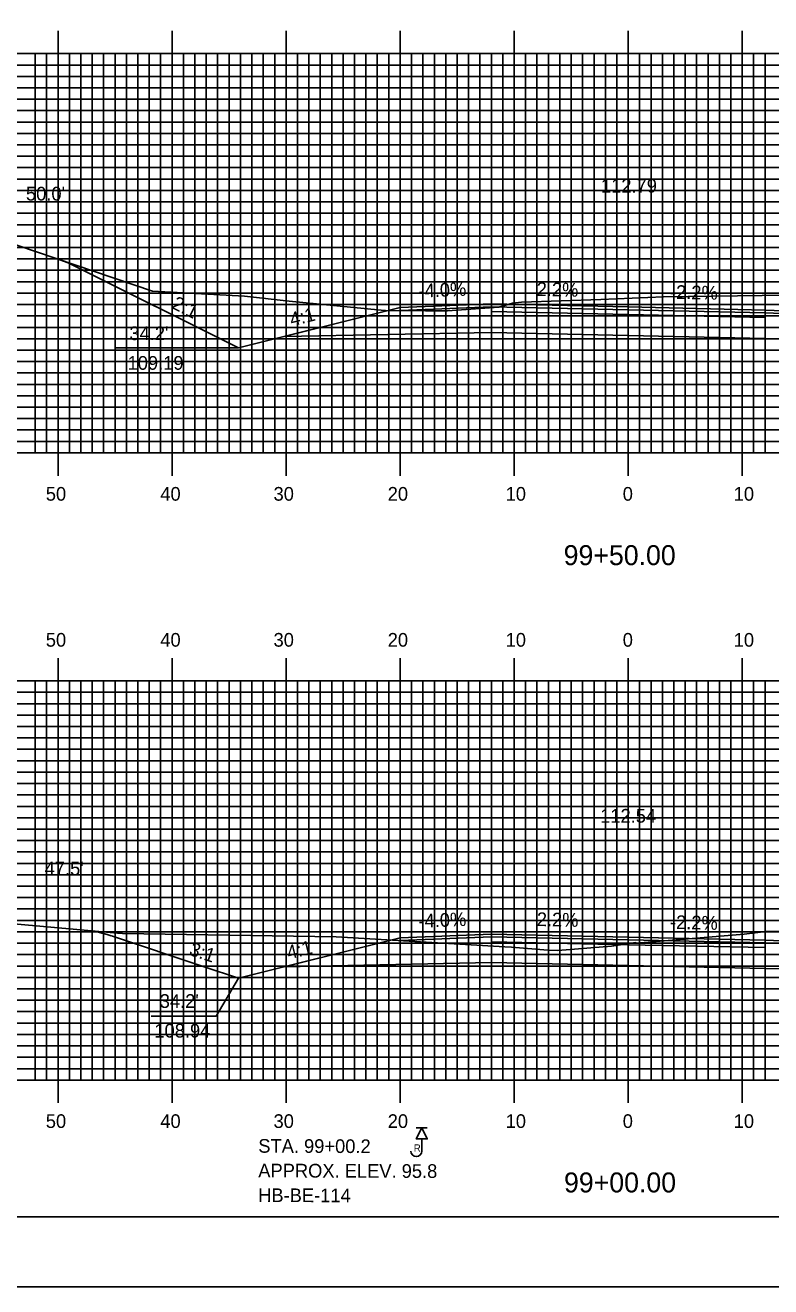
# Model space of a CAD drawing. Extents: x 1766513 to 1766856, y 442591 to 442811.
# Drawn here: x 1766626 to 1766691.4, y 442590.5 to 442701.2 of the extents above; entities that cross this region are included whole.
import ezdxf

# ---------------------------------------------------------------- set-up
doc = ezdxf.new("R2010")
doc.units = 0
for name, color, linetype in [('ANNOTATION', 7, 'Continuous'), ('BORDER', 7, 'Continuous'), ('BORING - REFUSAL', 7, 'Continuous'), ('D_Roadway_Centerline', 7, 'Continuous'), ('D_Roadway_Centerline_Text', 7, 'Continuous'), ('D_Roadway_Edge_Shoulder', 7, 'Continuous'), ('D_Roadway_Edge_TW', 7, 'Continuous'), ('D_Roadway_Pavement', 7, 'Continuous'), ('D_Roadway_SlopeLines', 7, 'Continuous'), ('D_Roadway_SubGrade', 7, 'Continuous'), ('D_Text_Standard', 7, 'Continuous'), ('H_V ANNOTATION', 7, 'Continuous'), ('MAJOR', 7, 'Continuous'), ('MINOR', 7, 'Continuous'), ('PDRAIN', 7, 'Continuous'), ('PLOT BOUNDARY', 7, 'Continuous'), ('S_Roadway_Centerline', 7, 'Continuous')]:
    doc.layers.add(name, color=color, linetype=linetype)

msp = doc.modelspace()

# ---------------------------------------------------------------- linework, layer by layer
at = {"layer": 'ANNOTATION'}
msp.add_lwpolyline([(1766637.09, 442614.28), (1766642.78, 442614.28), (1766644.74, 442617.61)], dxfattribs=at)
msp.add_arc((1766625.79, 442671.15), 10, 63.4315, 71.3181, dxfattribs=at)
at = {"layer": 'BORDER'}
msp.add_lwpolyline([(1766529.31, 442596.67), (1766849.31, 442596.67), (1766849.31, 442806.67), (1766529.31, 442806.67)], close=True, dxfattribs=at)
at = {"layer": 'BORING - REFUSAL'}
for p, q in [((1766661.29, 442604.47), (1766660.33, 442604.47)), ((1766660.81, 442603.51), (1766660.81, 442602.45))]:
    msp.add_line(p, q, dxfattribs=at)
msp.add_lwpolyline([(1766660.81, 442604.47), (1766661.29, 442603.51), (1766660.33, 442603.51)], close=True, dxfattribs=at)
msp.add_arc((1766660.33, 442602.45), 0.485, 180, 0, dxfattribs=at)
at = {"layer": 'D_Roadway_Centerline'}
for p, q in [((1766641.74, 442618.61), (1766633.59, 442621.32)), ((1766644.74, 442617.61), (1766641.74, 442618.61))]:
    msp.add_line(p, q, dxfattribs=at)
msp.add_arc((1766630.42, 442611.84), 10, 71.5651, 84.7849, dxfattribs=at)
at = {"layer": 'D_Roadway_Edge_Shoulder'}
for points in [[(1766666.91, 442676.72), (1766658.91, 442676.4), (1766658.91, 442676.15), (1766666.91, 442676.47)], [(1766690.91, 442676.19), (1766698.91, 442675.87), (1766698.91, 442675.62), (1766690.91, 442675.94)], [(1766666.91, 442621.47), (1766658.91, 442621.15), (1766658.91, 442620.9), (1766666.91, 442621.22)], [(1766690.91, 442620.94), (1766698.91, 442620.62), (1766698.91, 442620.37), (1766690.91, 442620.69)]]:
    msp.add_lwpolyline(points, close=True, dxfattribs=at)
at = {"layer": 'D_Roadway_Edge_TW'}
for points in [[(1766666.91, 442676.47), (1766666.91, 442676.72), (1766678.91, 442676.46), (1766690.91, 442676.19), (1766690.91, 442675.94), (1766678.91, 442676.21)], [(1766666.91, 442621.22), (1766666.91, 442621.47), (1766678.91, 442621.21), (1766690.91, 442620.94), (1766690.91, 442620.69), (1766678.91, 442620.96)]]:
    msp.add_lwpolyline(points, close=True, dxfattribs=at)
at = {"layer": 'D_Roadway_Pavement'}
for points in [[(1766666.91, 442676.05), (1766666.91, 442676.47), (1766678.91, 442676.21), (1766690.91, 442675.94), (1766690.91, 442675.53), (1766678.91, 442675.79)], [(1766666.91, 442620.8), (1766666.91, 442621.22), (1766678.91, 442620.96), (1766690.91, 442620.69), (1766690.91, 442620.28), (1766678.91, 442620.54)]]:
    msp.add_lwpolyline(points, close=True, dxfattribs=at)
at = {"layer": 'D_Roadway_SlopeLines'}
for points in [[(1766644.74, 442672.86), (1766630.26, 442680.09)], [(1766658.91, 442676.4), (1766644.74, 442672.86)], [(1766658.91, 442621.15), (1766644.74, 442617.61)]]:
    msp.add_lwpolyline(points, dxfattribs=at)
at = {"layer": 'D_Roadway_SubGrade'}
for points in [[(1766666.91, 442674.22), (1766648.74, 442673.86), (1766658.91, 442676.4), (1766658.91, 442676.15), (1766666.91, 442676.47), (1766678.91, 442676.21), (1766690.91, 442675.94), (1766698.91, 442675.62), (1766698.91, 442675.87), (1766709.08, 442673.33), (1766690.91, 442673.69), (1766678.91, 442673.96)], [(1766666.91, 442618.97), (1766648.74, 442618.61), (1766658.91, 442621.15), (1766658.91, 442620.9), (1766666.91, 442621.22), (1766678.91, 442620.96), (1766690.91, 442620.69), (1766698.91, 442620.37), (1766698.91, 442620.62), (1766709.08, 442618.08), (1766690.91, 442618.44), (1766678.91, 442618.71)]]:
    msp.add_lwpolyline(points, close=True, dxfattribs=at)
at = {"layer": 'MAJOR'}
for p, q in [((1766628.91, 442700.67), (1766628.91, 442698.67)), ((1766638.91, 442700.67), (1766638.91, 442698.67)), ((1766648.91, 442700.67), (1766648.91, 442698.67)), ((1766658.91, 442700.67), (1766658.91, 442698.67)), ((1766668.91, 442700.67), (1766668.91, 442698.67)), ((1766678.91, 442700.67), (1766678.91, 442698.67)), ((1766688.91, 442700.67), (1766688.91, 442698.67)), ((1766538.91, 442698.67), (1766818.91, 442698.67)), ((1766538.91, 442698.67), (1766818.91, 442698.67)), ((1766628.91, 442663.67), (1766628.91, 442698.67)), ((1766638.91, 442663.67), (1766638.91, 442698.67)), ((1766648.91, 442663.67), (1766648.91, 442698.67)), ((1766658.91, 442663.67), (1766658.91, 442698.67)), ((1766668.91, 442663.67), (1766668.91, 442698.67)), ((1766678.91, 442663.67), (1766678.91, 442698.67)), ((1766688.91, 442663.67), (1766688.91, 442698.67)), ((1766538.91, 442693.67), (1766818.91, 442693.67)), ((1766538.91, 442688.67), (1766818.91, 442688.67)), ((1766538.91, 442683.67), (1766818.91, 442683.67)), ((1766538.91, 442678.67), (1766818.91, 442678.67)), ((1766538.91, 442673.67), (1766818.91, 442673.67)), ((1766538.91, 442668.67), (1766818.91, 442668.67)), ((1766538.91, 442663.67), (1766818.91, 442663.67)), ((1766538.91, 442663.67), (1766818.91, 442663.67)), ((1766628.91, 442661.66), (1766628.91, 442663.67)), ((1766638.91, 442661.66), (1766638.91, 442663.67)), ((1766648.91, 442661.66), (1766648.91, 442663.67)), ((1766658.91, 442661.66), (1766658.91, 442663.67)), ((1766668.91, 442661.66), (1766668.91, 442663.67)), ((1766678.91, 442661.66), (1766678.91, 442663.67)), ((1766688.91, 442661.66), (1766688.91, 442663.67)), ((1766628.91, 442645.67), (1766628.91, 442643.67)), ((1766638.91, 442645.67), (1766638.91, 442643.67)), ((1766648.91, 442645.67), (1766648.91, 442643.67)), ((1766658.91, 442645.67), (1766658.91, 442643.67)), ((1766668.91, 442645.67), (1766668.91, 442643.67)), ((1766678.91, 442645.67), (1766678.91, 442643.67)), ((1766688.91, 442645.67), (1766688.91, 442643.67)), ((1766538.91, 442643.67), (1766818.91, 442643.67)), ((1766538.91, 442643.67), (1766818.91, 442643.67)), ((1766628.91, 442608.67), (1766628.91, 442643.67)), ((1766638.91, 442608.67), (1766638.91, 442643.67)), ((1766648.91, 442608.67), (1766648.91, 442643.67)), ((1766658.91, 442608.67), (1766658.91, 442643.67)), ((1766668.91, 442608.67), (1766668.91, 442643.67)), ((1766678.91, 442608.67), (1766678.91, 442643.67)), ((1766688.91, 442608.67), (1766688.91, 442643.67)), ((1766538.91, 442638.67), (1766818.91, 442638.67)), ((1766538.91, 442633.67), (1766818.91, 442633.67)), ((1766538.91, 442628.67), (1766818.91, 442628.67)), ((1766538.91, 442623.67), (1766818.91, 442623.67)), ((1766538.91, 442618.67), (1766818.91, 442618.67)), ((1766538.91, 442613.67), (1766818.91, 442613.67)), ((1766538.91, 442608.67), (1766818.91, 442608.67)), ((1766538.91, 442608.67), (1766818.91, 442608.67)), ((1766628.91, 442606.66), (1766628.91, 442608.67)), ((1766638.91, 442606.66), (1766638.91, 442608.67)), ((1766648.91, 442606.66), (1766648.91, 442608.67)), ((1766658.91, 442606.66), (1766658.91, 442608.67)), ((1766668.91, 442606.66), (1766668.91, 442608.67)), ((1766678.91, 442606.66), (1766678.91, 442608.67)), ((1766688.91, 442606.66), (1766688.91, 442608.67))]:
    msp.add_line(p, q, dxfattribs=at)
at = {"layer": 'MINOR'}
for p, q in [((1766626.91, 442663.67), (1766626.91, 442698.67)), ((1766627.91, 442663.67), (1766627.91, 442698.67)), ((1766629.91, 442663.67), (1766629.91, 442698.67)), ((1766630.91, 442663.67), (1766630.91, 442698.67)), ((1766631.91, 442663.67), (1766631.91, 442698.67)), ((1766632.91, 442663.67), (1766632.91, 442698.67)), ((1766633.91, 442663.67), (1766633.91, 442698.67)), ((1766634.91, 442663.67), (1766634.91, 442698.67)), ((1766635.91, 442663.67), (1766635.91, 442698.67)), ((1766636.91, 442663.67), (1766636.91, 442698.67)), ((1766637.91, 442663.67), (1766637.91, 442698.67)), ((1766639.91, 442663.67), (1766639.91, 442698.67)), ((1766640.91, 442663.67), (1766640.91, 442698.67)), ((1766641.91, 442663.67), (1766641.91, 442698.67)), ((1766642.91, 442663.67), (1766642.91, 442698.67)), ((1766643.91, 442663.67), (1766643.91, 442698.67)), ((1766644.91, 442663.67), (1766644.91, 442698.67)), ((1766645.91, 442663.67), (1766645.91, 442698.67)), ((1766646.91, 442663.67), (1766646.91, 442698.67)), ((1766647.91, 442663.67), (1766647.91, 442698.67)), ((1766649.91, 442663.67), (1766649.91, 442698.67)), ((1766650.91, 442663.67), (1766650.91, 442698.67)), ((1766651.91, 442663.67), (1766651.91, 442698.67)), ((1766652.91, 442663.67), (1766652.91, 442698.67)), ((1766653.91, 442663.67), (1766653.91, 442698.67)), ((1766654.91, 442663.67), (1766654.91, 442698.67)), ((1766655.91, 442663.67), (1766655.91, 442698.67)), ((1766656.91, 442663.67), (1766656.91, 442698.67)), ((1766657.91, 442663.67), (1766657.91, 442698.67)), ((1766659.91, 442663.67), (1766659.91, 442698.67)), ((1766660.91, 442663.67), (1766660.91, 442698.67)), ((1766661.91, 442663.67), (1766661.91, 442698.67)), ((1766662.91, 442663.67), (1766662.91, 442698.67)), ((1766663.91, 442663.67), (1766663.91, 442698.67)), ((1766664.91, 442663.67), (1766664.91, 442698.67)), ((1766665.91, 442663.67), (1766665.91, 442698.67)), ((1766666.91, 442663.67), (1766666.91, 442698.67)), ((1766667.91, 442663.67), (1766667.91, 442698.67)), ((1766669.91, 442663.67), (1766669.91, 442698.67)), ((1766670.91, 442663.67), (1766670.91, 442698.67)), ((1766671.91, 442663.67), (1766671.91, 442698.67)), ((1766672.91, 442663.67), (1766672.91, 442698.67)), ((1766673.91, 442663.67), (1766673.91, 442698.67)), ((1766674.91, 442663.67), (1766674.91, 442698.67)), ((1766675.91, 442663.67), (1766675.91, 442698.67)), ((1766676.91, 442663.67), (1766676.91, 442698.67)), ((1766677.91, 442663.67), (1766677.91, 442698.67)), ((1766679.91, 442663.67), (1766679.91, 442698.67)), ((1766680.91, 442663.67), (1766680.91, 442698.67)), ((1766681.91, 442663.67), (1766681.91, 442698.67)), ((1766682.91, 442663.67), (1766682.91, 442698.67)), ((1766683.91, 442663.67), (1766683.91, 442698.67)), ((1766684.91, 442663.67), (1766684.91, 442698.67)), ((1766685.91, 442663.67), (1766685.91, 442698.67)), ((1766686.91, 442663.67), (1766686.91, 442698.67)), ((1766687.91, 442663.67), (1766687.91, 442698.67)), ((1766689.91, 442663.67), (1766689.91, 442698.67)), ((1766690.91, 442663.67), (1766690.91, 442698.67)), ((1766538.91, 442697.67), (1766818.91, 442697.67)), ((1766538.91, 442696.67), (1766818.91, 442696.67)), ((1766538.91, 442695.67), (1766818.91, 442695.67)), ((1766538.91, 442694.67), (1766818.91, 442694.67)), ((1766538.91, 442692.67), (1766818.91, 442692.67)), ((1766538.91, 442691.67), (1766818.91, 442691.67)), ((1766538.91, 442690.67), (1766818.91, 442690.67)), ((1766538.91, 442689.67), (1766818.91, 442689.67)), ((1766538.91, 442687.67), (1766818.91, 442687.67)), ((1766538.91, 442686.67), (1766818.91, 442686.67)), ((1766538.91, 442685.67), (1766818.91, 442685.67)), ((1766538.91, 442684.67), (1766818.91, 442684.67)), ((1766538.91, 442682.67), (1766818.91, 442682.67)), ((1766538.91, 442681.67), (1766818.91, 442681.67)), ((1766538.91, 442680.67), (1766818.91, 442680.67)), ((1766538.91, 442679.67), (1766818.91, 442679.67)), ((1766538.91, 442677.67), (1766818.91, 442677.67)), ((1766538.91, 442676.67), (1766818.91, 442676.67)), ((1766538.91, 442675.67), (1766818.91, 442675.67)), ((1766538.91, 442674.67), (1766818.91, 442674.67)), ((1766538.91, 442672.67), (1766818.91, 442672.67)), ((1766538.91, 442671.67), (1766818.91, 442671.67)), ((1766538.91, 442670.67), (1766818.91, 442670.67)), ((1766538.91, 442669.67), (1766818.91, 442669.67)), ((1766538.91, 442667.67), (1766818.91, 442667.67)), ((1766538.91, 442666.67), (1766818.91, 442666.67)), ((1766538.91, 442665.67), (1766818.91, 442665.67)), ((1766538.91, 442664.67), (1766818.91, 442664.67)), ((1766626.91, 442608.67), (1766626.91, 442643.67)), ((1766627.91, 442608.67), (1766627.91, 442643.67)), ((1766629.91, 442608.67), (1766629.91, 442643.67)), ((1766630.91, 442608.67), (1766630.91, 442643.67)), ((1766631.91, 442608.67), (1766631.91, 442643.67)), ((1766632.91, 442608.67), (1766632.91, 442643.67)), ((1766633.91, 442608.67), (1766633.91, 442643.67)), ((1766634.91, 442608.67), (1766634.91, 442643.67)), ((1766635.91, 442608.67), (1766635.91, 442643.67)), ((1766636.91, 442608.67), (1766636.91, 442643.67)), ((1766637.91, 442608.67), (1766637.91, 442643.67)), ((1766639.91, 442608.67), (1766639.91, 442643.67)), ((1766640.91, 442608.67), (1766640.91, 442643.67)), ((1766641.91, 442608.67), (1766641.91, 442643.67)), ((1766642.91, 442608.67), (1766642.91, 442643.67)), ((1766643.91, 442608.67), (1766643.91, 442643.67)), ((1766644.91, 442608.67), (1766644.91, 442643.67)), ((1766645.91, 442608.67), (1766645.91, 442643.67)), ((1766646.91, 442608.67), (1766646.91, 442643.67)), ((1766647.91, 442608.67), (1766647.91, 442643.67)), ((1766649.91, 442608.67), (1766649.91, 442643.67)), ((1766650.91, 442608.67), (1766650.91, 442643.67)), ((1766651.91, 442608.67), (1766651.91, 442643.67)), ((1766652.91, 442608.67), (1766652.91, 442643.67)), ((1766653.91, 442608.67), (1766653.91, 442643.67)), ((1766654.91, 442608.67), (1766654.91, 442643.67)), ((1766655.91, 442608.67), (1766655.91, 442643.67)), ((1766656.91, 442608.67), (1766656.91, 442643.67)), ((1766657.91, 442608.67), (1766657.91, 442643.67)), ((1766659.91, 442608.67), (1766659.91, 442643.67)), ((1766660.91, 442608.67), (1766660.91, 442643.67)), ((1766661.91, 442608.67), (1766661.91, 442643.67)), ((1766662.91, 442608.67), (1766662.91, 442643.67)), ((1766663.91, 442608.67), (1766663.91, 442643.67)), ((1766664.91, 442608.67), (1766664.91, 442643.67)), ((1766665.91, 442608.67), (1766665.91, 442643.67)), ((1766666.91, 442608.67), (1766666.91, 442643.67)), ((1766667.91, 442608.67), (1766667.91, 442643.67)), ((1766669.91, 442608.67), (1766669.91, 442643.67)), ((1766670.91, 442608.67), (1766670.91, 442643.67)), ((1766671.91, 442608.67), (1766671.91, 442643.67)), ((1766672.91, 442608.67), (1766672.91, 442643.67)), ((1766673.91, 442608.67), (1766673.91, 442643.67)), ((1766674.91, 442608.67), (1766674.91, 442643.67)), ((1766675.91, 442608.67), (1766675.91, 442643.67)), ((1766676.91, 442608.67), (1766676.91, 442643.67)), ((1766677.91, 442608.67), (1766677.91, 442643.67)), ((1766679.91, 442608.67), (1766679.91, 442643.67)), ((1766680.91, 442608.67), (1766680.91, 442643.67)), ((1766681.91, 442608.67), (1766681.91, 442643.67)), ((1766682.91, 442608.67), (1766682.91, 442643.67)), ((1766683.91, 442608.67), (1766683.91, 442643.67)), ((1766684.91, 442608.67), (1766684.91, 442643.67)), ((1766685.91, 442608.67), (1766685.91, 442643.67)), ((1766686.91, 442608.67), (1766686.91, 442643.67)), ((1766687.91, 442608.67), (1766687.91, 442643.67)), ((1766689.91, 442608.67), (1766689.91, 442643.67)), ((1766690.91, 442608.67), (1766690.91, 442643.67)), ((1766538.91, 442642.67), (1766818.91, 442642.67)), ((1766538.91, 442641.67), (1766818.91, 442641.67)), ((1766538.91, 442640.67), (1766818.91, 442640.67)), ((1766538.91, 442639.67), (1766818.91, 442639.67)), ((1766538.91, 442637.67), (1766818.91, 442637.67)), ((1766538.91, 442636.67), (1766818.91, 442636.67)), ((1766538.91, 442635.67), (1766818.91, 442635.67)), ((1766538.91, 442634.67), (1766818.91, 442634.67)), ((1766538.91, 442632.67), (1766818.91, 442632.67)), ((1766538.91, 442631.67), (1766818.91, 442631.67)), ((1766538.91, 442630.67), (1766818.91, 442630.67)), ((1766538.91, 442629.67), (1766818.91, 442629.67)), ((1766538.91, 442627.67), (1766818.91, 442627.67)), ((1766538.91, 442626.67), (1766818.91, 442626.67)), ((1766538.91, 442625.67), (1766818.91, 442625.67)), ((1766538.91, 442624.67), (1766818.91, 442624.67)), ((1766538.91, 442622.67), (1766818.91, 442622.67)), ((1766538.91, 442621.67), (1766818.91, 442621.67)), ((1766538.91, 442620.67), (1766818.91, 442620.67)), ((1766538.91, 442619.67), (1766818.91, 442619.67)), ((1766538.91, 442617.67), (1766818.91, 442617.67)), ((1766538.91, 442616.67), (1766818.91, 442616.67)), ((1766538.91, 442615.67), (1766818.91, 442615.67)), ((1766538.91, 442614.67), (1766818.91, 442614.67)), ((1766538.91, 442612.67), (1766818.91, 442612.67)), ((1766538.91, 442611.67), (1766818.91, 442611.67)), ((1766538.91, 442610.67), (1766818.91, 442610.67)), ((1766538.91, 442609.67), (1766818.91, 442609.67))]:
    msp.add_line(p, q, dxfattribs=at)
at = {"layer": 'PDRAIN'}
msp.add_line((1766634.01, 442672.86), (1766644.74, 442672.86), dxfattribs=at)
at = {"layer": 'PLOT BOUNDARY'}
msp.add_lwpolyline([(1766513.12, 442590.55), (1766853.12, 442590.55), (1766853.12, 442810.55), (1766513.12, 442810.55)], close=True, dxfattribs=at)
at = {"layer": 'S_Roadway_Centerline'}
for points in [[(1766623.63, 442682.44), (1766637.21, 442677.84), (1766645.27, 442677.4), (1766649.17, 442676.97), (1766657.25, 442676.18), (1766657.64, 442676.16), (1766661.14, 442676.13), (1766663.07, 442676.11), (1766667.57, 442676.44), (1766668.75, 442676.8), (1766669.55, 442676.89), (1766676.5, 442677.12), (1766682.01, 442677.33), (1766690.67, 442677.46), (1766700.77, 442677.57), (1766708.39, 442677.48), (1766719.37, 442678.69), (1766721.75, 442678.96), (1766725.16, 442679.65), (1766756.32, 442687.64)], [(1766621.75, 442622.67), (1766634.14, 442621.54), (1766634.58, 442621.53), (1766653.29, 442621.23), (1766668.08, 442620.36), (1766668.67, 442620.31), (1766671.86, 442620.06), (1766672.75, 442620.03), (1766677.45, 442620.42), (1766679.57, 442620.72), (1766679.62, 442620.68), (1766689.07, 442621.45), (1766691.01, 442621.71), (1766695.11, 442621.7), (1766702.98, 442622.06), (1766717.96, 442623.39), (1766727.73, 442625.37), (1766738.03, 442628.92), (1766746.42, 442627.55)]]:
    msp.add_lwpolyline(points, dxfattribs=at)

# ---------------------------------------------------------------- texts
at = {"layer": 'ANNOTATION'}
for s, rotation, p in [('-4.0%', 2.2907, (1766660.54, 442677.27)), ('2.2%', 358.7397, (1766670.87, 442677.43)), ('-2.2%', 358.7397, (1766682.56, 442677.18)), ('2:1', 333.4315, (1766638.81, 442676.39)), ('4:1', 14.0391, (1766649.4, 442674.75)), ('-4.0%', 2.2906, (1766660.54, 442622.02)), ('2.2%', 358.7398, (1766670.88, 442622.18)), ('-2.2%', 358.7397, (1766682.56, 442621.93)), ('4:1', 14.0387, (1766649.14, 442619.24)), ('3:1', 341.5651, (1766640.34, 442619.66))]:
    msp.add_text(s, height=1.2, rotation=rotation, dxfattribs=at).set_placement(p)
for s, p in [("34.2'", (1766635.17, 442673.55)), ('109.19', (1766635.01, 442670.95)), ("34.2'", (1766637.83, 442615)), ('108.94', (1766637.36, 442612.4))]:
    msp.add_text(s, height=1.2, dxfattribs=at).set_placement(p)
at = {"layer": 'BORING - REFUSAL'}
for s, p in [('STA. 99+00.2', (1766646.47, 442602.3)), ('APPROX. ELEV. 95.8', (1766646.47, 442600.14)), ('HB-BE-114', (1766646.46, 442597.98))]:
    msp.add_text(s, height=1.2, rotation=359.8142, dxfattribs=at).set_placement(p)
msp.add_text('R', height=0.64, dxfattribs=at).set_placement((1766660.1, 442602.39))
at = {"layer": 'D_Roadway_Centerline'}
for s, p in [('C', (1766678.9, 442676.46)), ('L', (1766678.91, 442676.45)), ('C', (1766678.91, 442621.21)), ('L', (1766678.91, 442621.2))]:
    msp.add_text(s, height=0.0146, dxfattribs=at).set_placement(p)
at = {"layer": 'D_Roadway_Centerline_Text'}
for s, p in [('112.79', (1766676.52, 442686.49)), ('112.54', (1766676.45, 442631.24))]:
    msp.add_text(s, height=1.2, dxfattribs=at).set_placement(p)
at = {"layer": 'D_Text_Standard'}
for s, p in [("50.0'", (1766626.1, 442685.79)), ("47.5'", (1766627.74, 442626.63))]:
    msp.add_text(s, height=1.2, dxfattribs=at).set_placement(p)
at = {"layer": 'H_V ANNOTATION'}
for s, height, p in [('50', 1.2, (1766627.84, 442659.47)), ('40', 1.2, (1766637.88, 442659.47)), ('30', 1.2, (1766647.81, 442659.47)), ('20', 1.2, (1766657.82, 442659.47)), ('10', 1.2, (1766668.16, 442659.47)), ('0', 1.2, (1766678.43, 442659.47)), ('10', 1.2, (1766688.16, 442659.47)), ('99+50.00', 1.75, (1766673.25, 442653.82)), ('50', 1.2, (1766627.84, 442646.67)), ('40', 1.2, (1766637.88, 442646.67)), ('30', 1.2, (1766647.81, 442646.67)), ('20', 1.2, (1766657.82, 442646.67)), ('10', 1.2, (1766668.16, 442646.67)), ('0', 1.2, (1766678.43, 442646.67)), ('10', 1.2, (1766688.16, 442646.67)), ('50', 1.2, (1766627.84, 442604.47)), ('40', 1.2, (1766637.88, 442604.47)), ('30', 1.2, (1766647.81, 442604.47)), ('20', 1.2, (1766657.82, 442604.47)), ('10', 1.2, (1766668.16, 442604.47)), ('0', 1.2, (1766678.43, 442604.47)), ('10', 1.2, (1766688.16, 442604.47)), ('99+00.00', 1.75, (1766673.28, 442598.82))]:
    msp.add_text(s, height=height, dxfattribs=at).set_placement(p)

doc.saveas('drawing.dxf')
